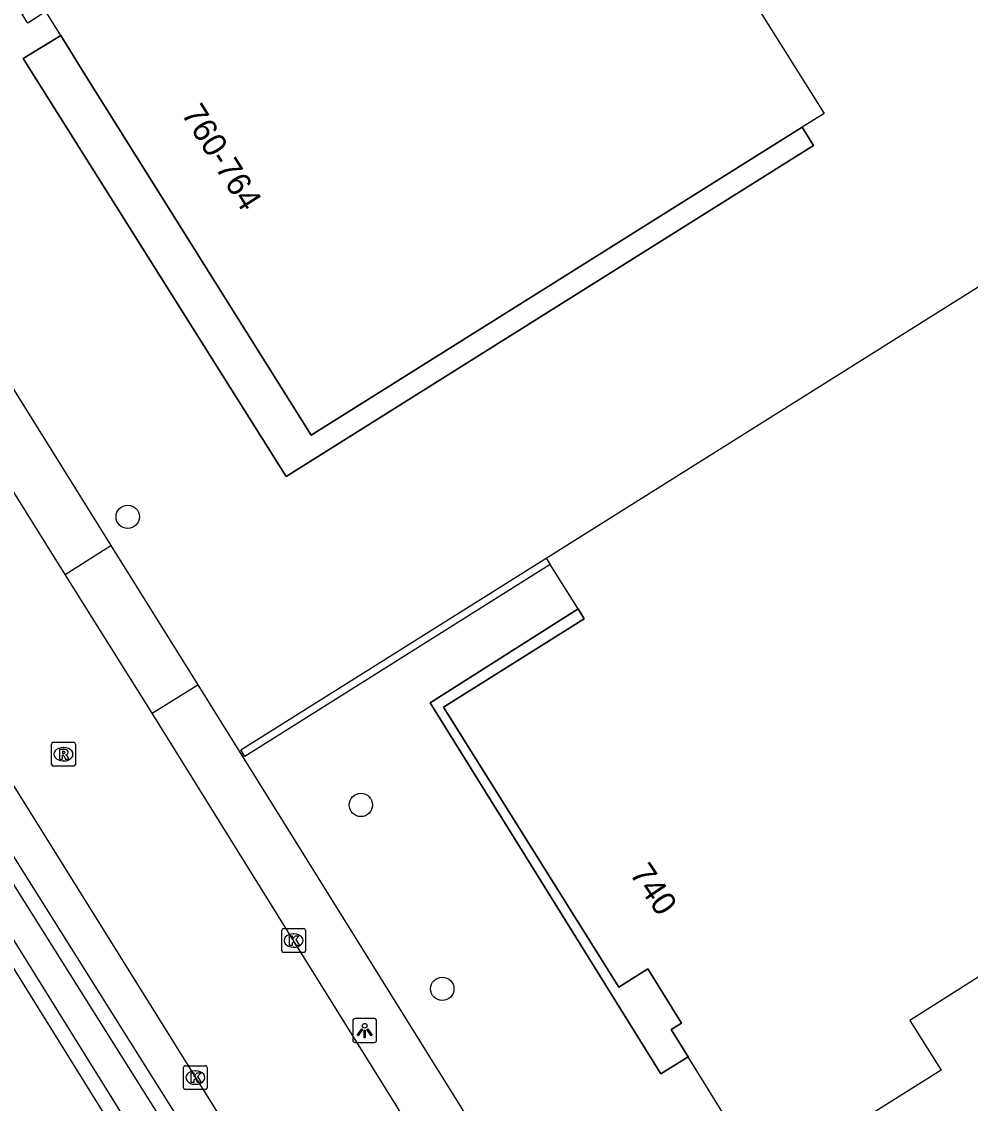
# Model space of a CAD drawing. Extents: x 158838 to 160074, y 386376 to 387776.
# Drawn here: x 159024.55 to 159064.34, y 386937.34 to 386982.71 of the extents above; entities that cross this region are included whole.
import ezdxf

# ---------------------------------------------------------------- set-up
doc = ezdxf.new("R2010")
doc.units = 0
for name, color, linetype in [('IMGEO_Berm_groen', 7, 'Continuous'), ('IMGEO_Boom', 7, 'Continuous'), ('IMGEO_Greppel_droge_sloot', 7, 'Continuous'), ('IMGEO_Kolk', 7, 'Continuous'), ('IMGEO_Lichtpunt', 7, 'Continuous'), ('IMGEO_Muur', 7, 'Continuous'), ('IMGEO_Pand', 7, 'Continuous'), ('IMGEO_Pand_nummerreeks', 7, 'Continuous'), ('IMGEO_Pand_overbouw', 7, 'Continuous'), ('IMGEO_Rijbaan_lokaal_open', 7, 'Continuous'), ('IMGEO_Rioolput', 7, 'Continuous'), ('IMGEO_Voetpad_open', 7, 'Continuous')]:
    doc.layers.add(name, color=color, linetype=linetype)

msp = doc.modelspace()

# ---------------------------------------------------------------- linework, layer by layer
at = {"layer": 'IMGEO_Berm_groen'}
msp.add_lwpolyline([(159000, 386986.242), (158991.693, 386999.224), (158990.004, 386998.024), (159000, 386981.943), (159035.265, 386925.216), (159055.682, 386892.626), (159088.981, 386839.474), (159089.256, 386838.78), (159089.835, 386838.498), (159090.244, 386838.524), (159091.028, 386838.871), (159091.422, 386839.242), (159091.568, 386839.665), (159091.508, 386840.108), (159063.62, 386885.019), (159057.921, 386894.086), (159000, 386986.242)], dxfattribs=at)
at = {"layer": 'IMGEO_Boom'}
for centre in [(159029.001, 386961.946), (159038.781, 386949.859), (159042.194, 386942.147)]:
    msp.add_circle(centre, 0.489, dxfattribs=at)
at = {"layer": 'IMGEO_Greppel_droge_sloot'}
msp.add_lwpolyline([(158999.473, 386985.908), (158991.52, 386998.336), (158991.091, 386998.031), (158990.844, 386997.855), (159000.53, 386982.272), (159035.794, 386925.546), (159056.211, 386892.957), (159089.54, 386839.757), (159089.747, 386839.235), (159089.96, 386839.131), (159090.093, 386839.14), (159090.678, 386839.399), (159090.882, 386839.591), (159090.93, 386839.728), (159090.907, 386839.892), (159063.091, 386884.688), (159057.393, 386893.754), (158999.473, 386985.908)], dxfattribs=at)
at = {"layer": 'IMGEO_Kolk'}
for p, q in [((159035.459, 386943.746), (159035.459, 386944.598)), ((159035.534, 386944.672), (159036.386, 386944.672)), ((159035.947, 386944.452), (159035.972, 386944.452)), ((159036.46, 386944.598), (159036.46, 386943.746)), ((159035.97, 386943.892), (159035.945, 386943.892)), ((159036.386, 386943.672), (159035.534, 386943.672)), ((159031.412, 386938.925), (159032.264, 386938.925)), ((159031.337, 386937.999), (159031.337, 386938.851)), ((159031.825, 386938.705), (159031.85, 386938.705)), ((159032.338, 386938.851), (159032.338, 386937.999)), ((159031.848, 386938.145), (159031.823, 386938.145)), ((159032.264, 386937.925), (159031.412, 386937.925))]:
    msp.add_line(p, q, dxfattribs=at)
for points in [[(159035.459, 386943.746), (159035.459, 386944.598)], [(159035.534, 386944.672), (159036.386, 386944.672)], [(159035.78, 386944.372), (159035.903, 386944.372), (159035.903, 386944.221), (159036.033, 386944.372), (159036.197, 386944.372), (159036.051, 386944.221), (159036.204, 386943.972), (159036.052, 386943.972), (159035.967, 386944.136), (159035.903, 386944.069), (159035.903, 386943.972), (159035.78, 386943.972), (159035.78, 386944.372)], [(159036.46, 386944.598), (159036.46, 386943.746)], [(159036.386, 386943.672), (159035.534, 386943.672)], [(159031.412, 386938.925), (159032.264, 386938.925)], [(159031.337, 386937.999), (159031.337, 386938.851)], [(159031.658, 386938.625), (159031.781, 386938.625), (159031.781, 386938.474), (159031.911, 386938.625), (159032.075, 386938.625), (159031.929, 386938.474), (159032.082, 386938.225), (159031.93, 386938.225), (159031.845, 386938.389), (159031.781, 386938.322), (159031.781, 386938.225), (159031.658, 386938.225), (159031.658, 386938.625)], [(159032.338, 386938.851), (159032.338, 386937.999)], [(159032.264, 386937.925), (159031.412, 386937.925)]]:
    msp.add_lwpolyline(points, dxfattribs=at)
for centre, start, end in [((159035.536, 386944.596), 91.552, 178.448), ((159035.536, 386944.596), 91.552, 178.448), ((159036.384, 386944.596), 1.552, 88.448), ((159036.384, 386944.596), 1.552, 88.448), ((159035.536, 386943.748), 181.552, 268.448), ((159035.536, 386943.748), 181.552, 268.448), ((159036.384, 386943.748), 271.552, 358.448), ((159036.384, 386943.748), 271.552, 358.448), ((159031.414, 386938.849), 91.552, 178.448), ((159031.414, 386938.849), 91.552, 178.448), ((159032.262, 386938.849), 1.552, 88.448), ((159032.262, 386938.849), 1.552, 88.448), ((159031.414, 386938.001), 181.552, 268.448), ((159031.414, 386938.001), 181.552, 268.448), ((159032.262, 386938.001), 271.552, 358.448), ((159032.262, 386938.001), 271.552, 358.448)]:
    msp.add_arc(centre, 0.0765, start, end, dxfattribs=at)
for centre, major_axis, ratio, start_param, end_param in [((159035.946, 386944.172), (-0.387, 0.002), 0.722429, 4.712389, 7.853982), ((159035.971, 386944.172), (-0.39, 0.002), 0.717154, 1.570796, 4.712389), ((159031.824, 386938.425), (-0.387, 0.002), 0.722429, 4.712389, 7.853982), ((159031.849, 386938.425), (-0.39, 0.002), 0.717154, 1.570796, 4.712389)]:
    msp.add_ellipse(centre, major_axis=major_axis, ratio=ratio, start_param=start_param, end_param=end_param, dxfattribs=at)
at = {"layer": 'IMGEO_Lichtpunt'}
for p, q in [((159038.442, 386940.802), (159038.442, 386939.995)), ((159038.442, 386940.802), (159038.442, 386939.995)), ((159039.344, 386940.897), (159038.536, 386940.897)), ((159039.344, 386940.897), (159038.536, 386940.897)), ((159039.438, 386939.995), (159039.438, 386940.802)), ((159039.438, 386939.995), (159039.438, 386940.802)), ((159038.536, 386939.901), (159039.344, 386939.901)), ((159038.536, 386939.901), (159039.344, 386939.901))]:
    msp.add_line(p, q, dxfattribs=at)
for points in [[(159038.816, 386940.466), (159038.855, 386940.438), (159038.667, 386940.176), (159038.629, 386940.203), (159038.816, 386940.466)], [(159038.918, 386940.418), (159038.965, 386940.418), (159038.965, 386940.096), (159038.918, 386940.096), (159038.918, 386940.418)], [(159039.028, 386940.438), (159039.066, 386940.465), (159039.253, 386940.203), (159039.214, 386940.175), (159039.028, 386940.438)]]:
    msp.add_lwpolyline(points, dxfattribs=at)
msp.add_circle((159038.941, 386940.6), 0.0994, dxfattribs=at)
for centre, start, end in [((159038.536, 386940.802), 90, 180), ((159038.536, 386940.802), 90, 180), ((159039.344, 386940.802), 0, 90), ((159039.344, 386940.802), 0, 90), ((159038.536, 386939.995), 180, 270), ((159038.536, 386939.995), 180, 270), ((159039.344, 386939.995), 270, 0), ((159039.344, 386939.995), 270, 360)]:
    msp.add_arc(centre, 0.0946, start, end, dxfattribs=at)
at = {"layer": 'IMGEO_Muur'}
msp.add_lwpolyline([(159046.725, 386959.948), (159033.917, 386951.894), (159033.752, 386952.168), (159046.555, 386960.214)], dxfattribs=at)
at = {"layer": 'IMGEO_Pand'}
for points in [[(159026.194, 386982.136), (159025.567, 386983.142), (159024.806, 386982.657), (159024.569, 386983.012), (159046.82, 386996.976), (159046.948, 386996.772), (159051.79, 386999.81), (159054.282, 386995.839), (159051.068, 386993.823), (159050.274, 386995.089), (159048.648, 386994.069), (159058.212, 386978.863), (159057.291, 386978.285)], [(159026.194, 386982.136), (159027.237, 386980.461), (159036.699, 386965.371), (159057.291, 386978.285)], [(159046.555, 386960.214), (159064.894, 386971.726), (159077.764, 386950.938), (159061.799, 386940.822), (159063.111, 386938.73), (159055.719, 386934.097), (159052.509, 386939.297)], [(159046.555, 386960.214), (159046.725, 386959.948)], [(159047.888, 386958.091), (159046.725, 386959.948)], [(159047.888, 386958.091), (159048.15, 386957.673), (159042.244, 386953.965), (159049.598, 386942.216), (159050.819, 386942.987), (159052.234, 386940.714), (159051.8, 386940.446), (159052.509, 386939.297)]]:
    msp.add_lwpolyline(points, dxfattribs=at)
at = {"layer": 'IMGEO_Pand_overbouw'}
for points in [[(159057.291, 386978.285), (159036.699, 386965.371), (159027.237, 386980.461), (159026.194, 386982.136), (159024.619, 386981.173), (159035.647, 386963.634), (159057.77, 386977.522)], [(159052.509, 386939.297), (159051.8, 386940.446), (159052.234, 386940.714), (159050.819, 386942.987), (159049.598, 386942.216), (159042.244, 386953.965), (159048.15, 386957.673), (159047.888, 386958.091), (159041.68, 386954.144), (159051.367, 386938.582)]]:
    msp.add_lwpolyline(points, close=True, dxfattribs=at)
at = {"layer": 'IMGEO_Rijbaan_lokaal_open'}
for points in [[(158992.734, 387001.043), (158993.387, 387000), (159000, 386989.439), (159000.316, 386988.934), (159010.09, 386973.23), (159021.504, 386954.997), (159031.839, 386938.426), (159043.257, 386920.182), (159053.024, 386904.489), (159059.057, 386894.827), (159065.997, 386883.711), (159075.251, 386868.876), (159086.653, 386850.613), (159097.471, 386833.198), (159108.33, 386815.791), (159119.183, 386798.375), (159120.937, 386795.51), (159121.337, 386794.968), (159121.784, 386794.465)], [(159026.376, 386959.526), (159015.823, 386976.434), (159015.665, 386976.654)], [(159030.023, 386953.704), (159026.376, 386959.526)], [(159044.207, 386930.937), (159035.958, 386944.171), (159030.023, 386953.704)]]:
    msp.add_lwpolyline(points, dxfattribs=at)
at = {"layer": 'IMGEO_Rioolput'}
for p, q in [((159025.804, 386951.561), (159025.804, 386952.413)), ((159025.879, 386952.487), (159026.731, 386952.487)), ((159026.292, 386952.267), (159026.317, 386952.267)), ((159026.805, 386952.413), (159026.805, 386951.561)), ((159026.315, 386951.707), (159026.29, 386951.707)), ((159026.731, 386951.487), (159025.879, 386951.487))]:
    msp.add_line(p, q, dxfattribs=at)
for points in [[(159025.804, 386951.561), (159025.804, 386952.413)], [(159025.879, 386952.487), (159026.731, 386952.487)], [(159026.393, 386952.185), (159026.141, 386952.187), (159026.141, 386951.787)], [(159026.319, 386952.106), (159026.265, 386952.106), (159026.265, 386952.025)], [(159026.805, 386952.413), (159026.805, 386951.561)], [(159026.141, 386951.787), (159026.265, 386951.787), (159026.265, 386951.949), (159026.276, 386951.949)], [(159026.265, 386952.025), (159026.317, 386952.025)], [(159026.323, 386951.92), (159026.394, 386951.787), (159026.534, 386951.787), (159026.469, 386951.913)], [(159026.731, 386951.487), (159025.879, 386951.487)]]:
    msp.add_lwpolyline(points, dxfattribs=at)
for centre, radius, start, end in [((159025.881, 386952.411), 0.0765, 91.552, 178.448), ((159025.881, 386952.411), 0.0765, 91.552, 178.448), ((159026.325, 386952.01), 0.0964, 77.0061, 93.1865), ((159026.339, 386952.067), 0.0378, 276.6634, 79.6772), ((159026.392, 386952.075), 0.109, 350.3612, 89.416), ((159026.39, 386952.075), 0.112, 277.5842, 350.9817), ((159026.729, 386952.411), 0.0765, 1.552, 88.448), ((159026.729, 386952.411), 0.0765, 1.552, 88.448), ((159026.275, 386951.896), 0.0533, 26.0293, 88.6989), ((159026.301, 386952.214), 0.19, 274.7715, 282.9687), ((159026.374, 386951.86), 0.108, 29.5134, 73.7905), ((159025.881, 386951.563), 0.0765, 181.552, 268.448), ((159025.881, 386951.563), 0.0765, 181.552, 268.448), ((159026.729, 386951.563), 0.0765, 271.552, 358.448), ((159026.729, 386951.563), 0.0765, 271.552, 358.448)]:
    msp.add_arc(centre, radius, start, end, dxfattribs=at)
for centre, major_axis, ratio, start_param, end_param in [((159026.291, 386951.987), (-0.387, 0.002), 0.722429, 4.712389, 7.853982), ((159026.316, 386951.987), (-0.39, 0.002), 0.717154, 1.570796, 4.712389)]:
    msp.add_ellipse(centre, major_axis=major_axis, ratio=ratio, start_param=start_param, end_param=end_param, dxfattribs=at)
at = {"layer": 'IMGEO_Voetpad_open'}
for points in [[(159057.291, 386978.285), (159057.77, 386977.522), (159035.647, 386963.634), (159024.619, 386981.173), (159026.194, 386982.136)], [(159017.609, 386977.869), (159028.298, 386960.742)], [(159026.376, 386959.526), (159028.298, 386960.742)], [(159028.298, 386960.742), (159031.942, 386954.904)], [(159052.509, 386939.297), (159051.367, 386938.582), (159041.68, 386954.144), (159047.888, 386958.091)], [(159030.023, 386953.704), (159031.942, 386954.904)], [(159031.942, 386954.904), (159046.121, 386932.132)]]:
    msp.add_lwpolyline(points, dxfattribs=at)

# ---------------------------------------------------------------- texts
at = {"layer": 'IMGEO_Pand_nummerreeks'}
for s, rotation, p in [('760-764', 302.0625, (159031.225, 386978.856)), ('740', 304.1462, (159050.025, 386946.981))]:
    msp.add_text(s, height=1, rotation=rotation, dxfattribs=at).set_placement(p)

doc.saveas('drawing.dxf')
